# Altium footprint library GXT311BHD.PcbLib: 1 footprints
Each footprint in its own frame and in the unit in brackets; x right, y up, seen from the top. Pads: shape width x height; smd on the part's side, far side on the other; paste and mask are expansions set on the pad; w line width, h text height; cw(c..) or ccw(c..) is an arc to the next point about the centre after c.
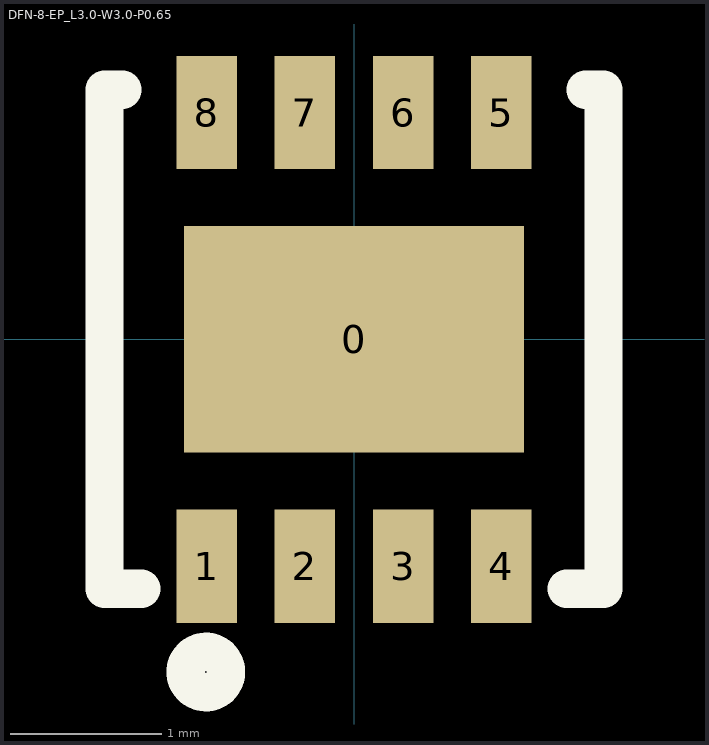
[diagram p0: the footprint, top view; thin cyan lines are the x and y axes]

## DFN-8-EP_L3.0-W3.0-P0.65 [mm]
pads (9):
  rect 2.25x1.5 smd: 0(0,0)
  rect 0.4x0.75 smd: 1(-0.975,-1.5) 2(-0.325,-1.5) 3(0.325,-1.5) 4(0.975,-1.5) 5(0.975,1.5) 6(0.325,1.5) 7(-0.325,1.5) 8(-0.975,1.5)
Top Overlay:
  circle w0.254: c-0.98,-2.2 r0.133
  lines w0.254: -1.531,1.65 -1.65,1.65 -1.65,-1.65 -1.406,-1.65 ; 1.406,-1.65 1.65,-1.65 1.65,1.65 1.531,1.65
3D body "DFN-8-EP_L3.0-W3.0-P0.65.STEP": height 0.62, standoff 0, extent -1.496,-1.51 1.524,1.51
